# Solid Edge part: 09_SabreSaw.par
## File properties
Author: edge
Template: normal.par
Last saved by: edge
Revision: 134
Application: Solid Edge
Material: ABS プラスチック, 高インパクト
面のスタイル: Tan
塗りつぶしのスタイル: ANSI34(Plastic)
バーチャルスタイル: 赤（シャイニー）
Coef. of Thermal Exp: 0.0
Thermal Conductivity: 0.2
Specific Heat: 0.0
Modulus of Elasticity: 1378951400.0
Poisson's Ratio: 0.4
Yield Stress: 31026406.5
Ultimate Stress: 0.0
Elongation: 0.0
非切断部品: False
文書内容のタイプ: 0
Density: 0.03699434701 lbm/in^3
Accuracy: 0.99
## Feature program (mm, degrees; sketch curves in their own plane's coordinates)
pattern "unnamed Pattern 1"
Other named dimensions: "Hole_22": CounterBoreDiameter = 8 mm
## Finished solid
Body 1: solid body, 849 faces, 2185 edges, 1328 vertices.
  Faces by surface: plane 372, blend 233, cone 105, cylinder 74, torus 39, offset 18, swept 5, spline 3
  Edges by curve: line 890, intersection 647, circle 437, ellipse 187, curve on surface 24
Body 2: solid body, 7 faces, 15 edges, 10 vertices.
  Faces by surface: plane 4, spline 3
  Edges by curve: line 8, spline 3, circle 2, curve on surface 2
Body 3: solid body, 6 faces, 14 edges, 10 vertices.
  Faces by surface: spline 4, plane 2
  Edges by curve: curve on surface 6, line 5, spline 2, ellipse 1
Body 4: sheet body, 1 face, 6 edges, 6 vertices.
  Faces by surface: offset 1
  Edges by curve: curve on surface 4, line 2
Bounding box of the edges (mm; curved faces can reach further): 213.688 x 195.524 x 51.185, from (-84.0788, -83.9606, -49.1848) to (129.6096, 111.5634, 2).
Cylindrical faces by radius (mm): R0.5 x4, R1 x7, R2 x12, R2.25 x1, R2.5 x5, R3 x4, R3.5 x3, R4 x1, R4.5 x3, R5 x5, R7.5 x3, R8 x2, R8.255 x1, R9.5 x2, R10 x2, R11 x1, R12 x2, R12.5 x2, R14 x1, R15 x1, R20 x1, R97.5 x1, R100 x2, R102.5 x2, R152.4372 x1, R154.9372 x1, R237.1007 x3, R239.6007 x1
Conical faces (half-angle, radius in mm at the cone's reference point): 1 deg R2.25 x12, 1 deg R4 x12, 1 deg R4.5 x13, 1 deg R6 x13, 1 deg R14 x1, 2 deg R4 x2, 2 deg R5 x10, 2 deg R7.4985 x6, 2 deg R10 x4, 2 deg R12.4985 x4, 2 deg R15 x2, 2 deg R17.4985 x2, 2 deg R17.5015 x2, 2 deg R20 x2, 2 deg R47.5015 x1, 2 deg R50 x1, 2 deg R57.5015 x3, 2 deg R60 x1, 2 deg R138 x1, 2 deg R140 x1, 2 deg R140.4985 x2, 2 deg R142.4985 x2, 2 deg R184.4634 x3, 2 deg R186.9618 x1, 2 deg R197.5015 x3, 2 deg R200 x1
Toroidal faces (ring radius, tube radius in mm): R-185.2857 r347.5 x1, R-185.2857 r350 x2, R-100.6221 r347.5 x4, R-100.6221 r350 x1, R4.0343 r1 x2, R4.0343 r3.5 x2, R5.2271 r1 x2, R5.5413 r1 x2, R6 r1 x2, R7.358 r1 x6, R7.6722 r1 x1, R16.2253 r5 x1, R54.9372 r97.5 x2, R54.9372 r100 x1, R139.6007 r97.5 x4, R139.6007 r100 x1, R229.9372 r100 x1, R229.9372 r102.5 x1, R314.6007 r100 x1, R314.6007 r102.5 x2
Planar faces by outward normal: +x 1, +z 85, -x 1, -z 19, oblique 272
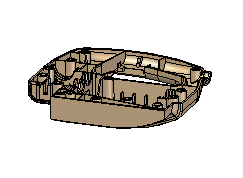
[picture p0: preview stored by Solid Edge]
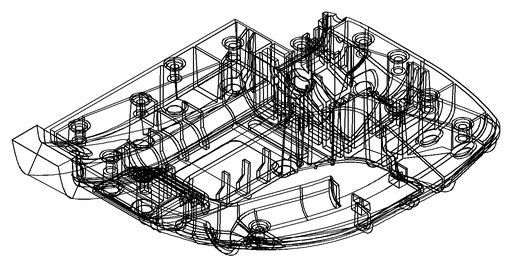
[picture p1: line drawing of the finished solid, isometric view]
